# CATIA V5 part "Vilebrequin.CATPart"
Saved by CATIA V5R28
Part number: Vilebrequin
Bounding box of the stored display mesh (mm): x -74 to 6, y -12.999 to 12.999, z -15.344 to 15.5
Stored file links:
  D:\Back up\Mission d'enseignement\TP Catia\2 oct - Assemblage\Vilebrequin.CATPart
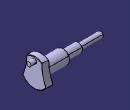
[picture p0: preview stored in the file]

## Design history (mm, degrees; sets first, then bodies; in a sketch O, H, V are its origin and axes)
Body1 (main body)
  Sketch1 on xy-plane, origin (0, 0, 0), H (1, 0, 0), V (0, 1, 0)
    line L1 (0, 0) -> (-74, 0)
    line L2 (-74, 0) -> (-74, 3)
    line L3 (-74, 3) -> (-49, 3)
    line L4 (-49, 3) -> (-49, 5)
    line L5 (-49, 5) -> (-32, 5)
    line L6 (-32, 5) -> (-32, 7.5)
    line L7 (-32, 7.5) -> (-8, 7.5)
    line L8 (-8, 7.5) -> (-8, 8)
    line L9 (-8, 8) -> (-7.5, 8)
    line L10 (-7.5, 8) -> (-7.5, 15.5)
    line L11 (-7.5, 15.5) -> (0, 15.5)
    point P11 (0, 15.5)
    line L12 (0, 15.5) -> (0, 0)
    length L3 = 25
    length L5 = 17
    length L7 = 24
    length L9 = 0.5
    length L11 = 7.5
    distance L3 L1 = 3
    distance L5 L1 = 5
    distance L7 L1 = 7.5
    distance L9 L7 = 0.5
    distance L11 L1 = 15.5
    horizontal: L1 H, L3 H, L5 H, L7 H, L9 H, L11 H
    vertical: L2 V, L4 V, L6 V, L8 V, L10 V, L12 V
    coincidence: P11 V
  Shaft1: profile Sketch1, axis X axis, angle 360
  Sketch2 on face of Shaft1 from Sketch1.L12, origin (0, 0, 0), H (0, 1, 0), V (0, 0, 1)
    arc A1 centre (-53.4118, 11.353) radius 45 from (-12.9994, -8.4419) to (-8.4419, 12.9994) ccw
    point P2 (-12.9994, -8.4419)
    point P3 (-8.4419, 12.9994)
    construction line L1 (-8.4419, 12.9994) -> (-12.9994, -8.4419)
    point P4 (-8.4419, 12.9994)
    point P5 (-12.9994, -8.4419)
    construction line L2 (0, 0) -> (0, -25.9812)
    reference projected circle E1 centre (0, 0) radius 15.5 from edge [face of Shaft1 from Sketch1.L11 | face of Shaft1 from Sketch1.L12]
    reference projected circle E2 centre (0, 0) radius 15.5 from edge [face of Shaft1 from Sketch1.L11 | face of Shaft1 from Sketch1.L12]
    construction line L3 (0, 0) -> (-8.4419, 12.9994)
    axis line L4 (0, 0) -> (-12.9994, -8.4419)
    arc A2 centre (0, 0) radius 15.5 from (-8.4419, 12.9994) to (-12.9994, -8.4419) ccw
    radius A1 = 45
    angle L1 L2 = 12
    angle L3 L4 = 90
    vertical: L2 V
    coincidence: P4 E1, P5 E2, P3 P4, P2 P5
  Pocket1: profile Sketch2, direction (-1, 0, 0), through (limit type 6)
  Mirror1: of Pocket1, about zx-plane
  Sketch3 on face of Shaft1 from Sketch1.L12, origin (0, 0, 0), H (0, 1, 0), V (0, 0, 1)
    circle A1 centre (0, 11) radius 2.5
    point P1 (0, 11)
    radius A1 = 2.5
    distance P1 O = 11
    coincidence: P1 V
  Pad1: profile Sketch3, direction (1, 0, 0), length 6
  Chamfer1: length 0.5, angle 45, on edge [face of Shaft1 from Sketch1.L2 | face of Shaft1 from Sketch1.L3]; edge [face of Shaft1 from Sketch1.L4 | face of Shaft1 from Sketch1.L5]; edge [face of Shaft1 from Sketch1.L6 | face of Shaft1 from Sketch1.L7]; edge [face of Shaft1 from Sketch1.L10 | face of Shaft1 from Sketch1.L11] (x2); edge [face of Shaft1 from Sketch1.L11 | face of Shaft1 from Sketch1.L12] (x2)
